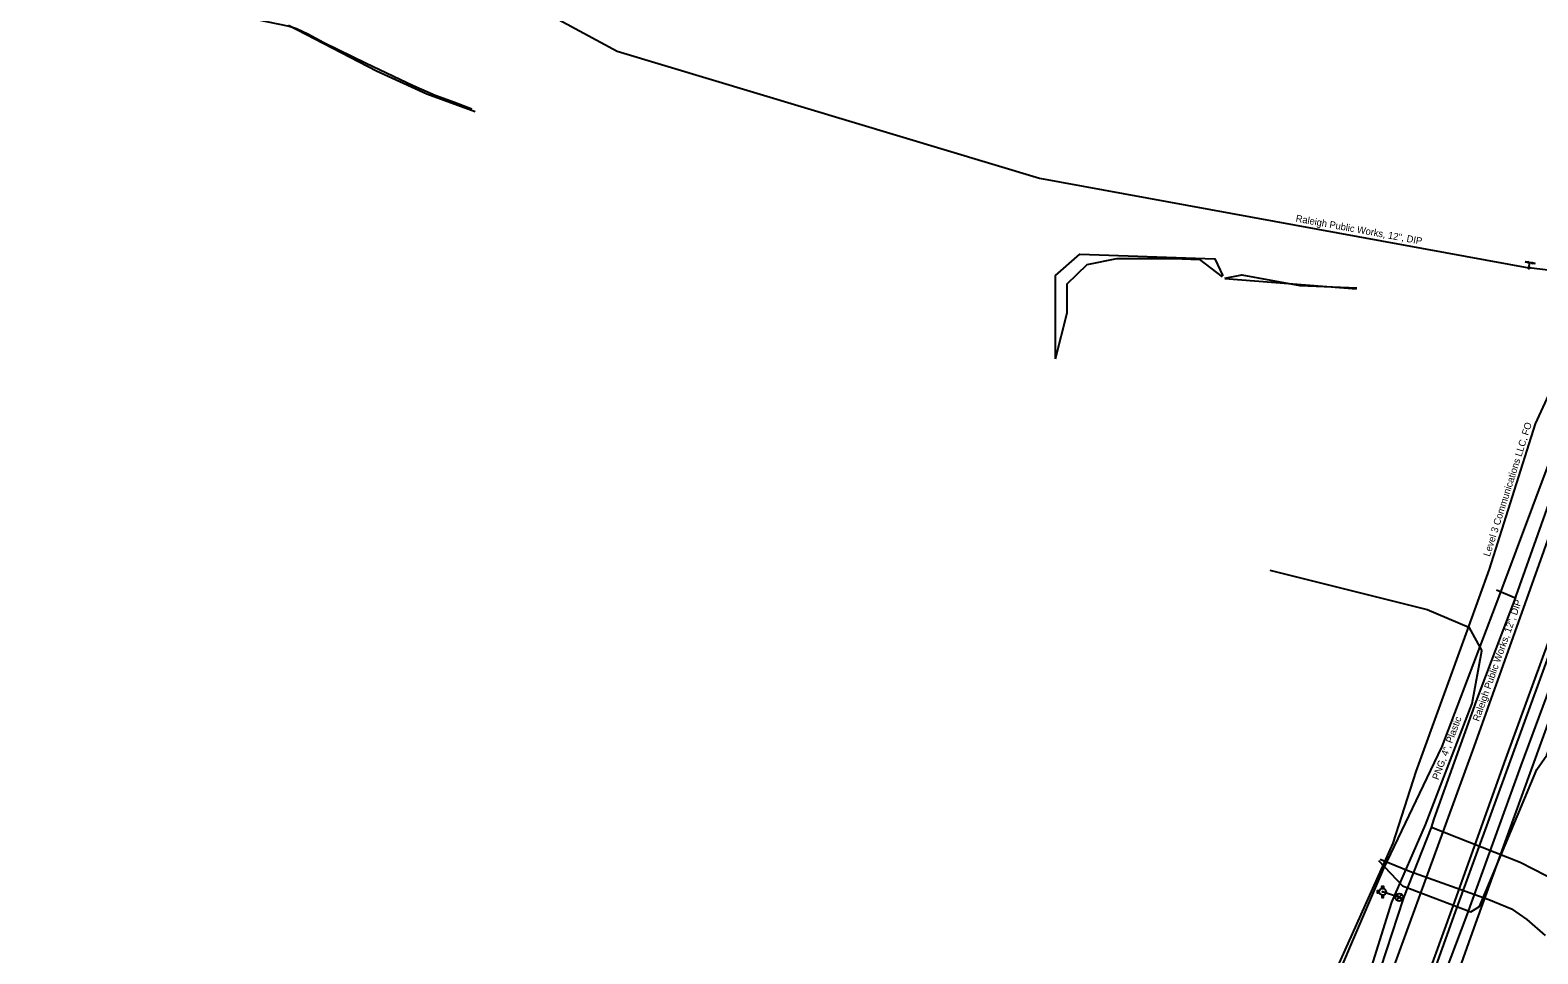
# Model space of a CAD drawing. Extents: x 2070721 to 2083340, y 729290 to 737883.
# Drawn here: x 2080348 to 2081213, y 733305 to 733835 of the extents above; entities that cross this region are included whole.
import ezdxf

# ---------------------------------------------------------------- set-up
doc = ezdxf.new("R2010")
doc.units = 0
for name, color, linetype in [('Exist Utilities Gas UG Line SUE LOS B', 7, 'Continuous'), ('Exist Utilities Gas UG Line SUE LOS B Text', 7, 'Continuous'), ('Exist Utilities Power UG Cable SUE LOS B', 7, 'Continuous'), ('Exist Utilities Telephone UG Cable SUE LOS C', 7, 'Continuous'), ('Exist Utilities Telephone UG FO SUE LOS B', 7, 'Continuous'), ('Exist Utilities Telephone UG FO SUE LOS B Text', 7, 'Continuous'), ('Exist Utilities TV UG Cable SUE LOS B', 7, 'Continuous'), ('Exist Utilities TV UG Cable SUE LOS C', 7, 'Continuous'), ('Exist Utilities TV UG FO Cable SUE LOS B', 7, 'Continuous'), ('Exist Utilities Water Change of Service SUE CELL', 7, 'Continuous'), ('Exist Utilities Water Fire Hydrant CELL', 7, 'Continuous'), ('Exist Utilities Water UG Line SUE LOS B', 7, 'Continuous'), ('Exist Utilities Water UG Line SUE LOS B Text', 7, 'Continuous'), ('Exist Utilities Water UG Line SUE LOS C', 7, 'Continuous'), ('Exist Utilities Water UG Line SUE LOS C Text', 7, 'Continuous'), ('Exist Utilities Water Valve CELL', 7, 'Continuous')]:
    doc.layers.add(name, color=color, linetype=linetype)

msp = doc.modelspace()

# ---------------------------------------------------------------- linework, layer by layer
at = {"layer": 'Exist Utilities Gas UG Line SUE LOS B'}
for points in [[(2081157.6, 733423.49), (2081157.75, 733423.93), (2081190.43, 733509.93), (2081219.7, 733588.19), (2081252.91, 733674.58), (2081286.02, 733770.88), (2081302.57, 733820.59), (2081312.47, 733846.89)], [(2080924.17, 732884.04), (2080930.33, 732882.17), (2080949.02, 732923.62), (2080986.84, 733002.49), (2081018.88, 733098.52), (2081046.79, 733177.28), (2081082.41, 733256.43), (2081124.09, 733353.56), (2081157.6, 733423.49)]]:
    msp.add_lwpolyline(points, dxfattribs=at)
at = {"layer": 'Exist Utilities Power UG Cable SUE LOS B'}
msp.add_line((2081108.69, 733686.24), (2081033.23, 733692.12), dxfattribs=at)
for points in [[(2081033.19, 733692.45), (2081042.88, 733694.33), (2081076.25, 733688.25), (2081108.94, 733687)], [(2081122.35, 733359.34), (2081139.09, 733352.49), (2081184.49, 733336.32), (2081197.51, 733330.86), (2081206.4, 733324.71), (2081216.97, 733315.56)]]:
    msp.add_lwpolyline(points, dxfattribs=at)
at = {"layer": 'Exist Utilities Telephone UG Cable SUE LOS C'}
for points in [[(2080953.21, 732796.69), (2081054.09, 733077.62), (2081111.09, 733245.57), (2081176.08, 733423.78), (2081231.97, 733580.28), (2081320.16, 733847.08), (2081418.84, 734093.09), (2081467.34, 734224.03), (2081494.06, 734287.2), (2081526.74, 734352.01), (2081556, 734404.62), (2081808.13, 734757.73), (2081845.73, 734804.26), (2081874.67, 734821.58), (2081898.66, 734810.94), (2081917.15, 734795.51)], [(2080936, 733646.3), (2080936, 733671.46), (2080936, 733693.97), (2080950.03, 733706.27), (2081027.4, 733703.51), (2081032.1, 733693.76)], [(2080936, 733646.3), (2080942.8, 733672.51), (2080942.8, 733689.3), (2080954.18, 733700.25), (2080971.23, 733703.78), (2081003.67, 733703.78), (2081018.65, 733703.13), (2081031.75, 733693.2)], [(2080971.45, 732791.05), (2081028.93, 732955.93), (2081037.58, 732965.12), (2081059.34, 733032.5), (2081099.5, 733145.5), (2081127.24, 733222.27), (2081165.53, 733329.08), (2081197.08, 733415.76), (2081225.51, 733493.81), (2081252.34, 733568.18), (2081252.65, 733568.73)], [(2080977.85, 732787.5), (2081009.55, 732879.6), (2081045.87, 732978.13), (2081063.56, 733030.35), (2081103.18, 733143.81), (2081131.57, 733220.23), (2081172.06, 733327.38), (2081203.1, 733413.05), (2081232.13, 733491.49), (2081257.07, 733565.11), (2081257.51, 733566.68)], [(2080980.31, 732787.04), (2081017.13, 732880.26), (2081044.65, 732962.53), (2081058.02, 732999.54), (2081069.26, 733036.84), (2081073.31, 733048.09), (2081079.75, 733057.99), (2081085.51, 733069.49), (2081110.84, 733140.06), (2081139.9, 733217.95), (2081177.19, 733322.59), (2081208.97, 733410.75), (2081237.5, 733489.4), (2081264.77, 733561.01)], [(2081059.04, 733525.1), (2081149.16, 733502.55), (2081173.19, 733492.4), (2081180.53, 733478.86)], [(2080944.31, 732798.44), (2080951.65, 732814.71), (2080971.81, 732874.01), (2081001.7, 732960.05), (2081020.52, 733019.4), (2081051.78, 733107.87), (2081085.75, 733202.6), (2081111.57, 733279.04), (2081128.94, 733334.77), (2081148.26, 733379.04), (2081175.1, 733448.52), (2081180.53, 733478.86)]]:
    msp.add_lwpolyline(points, dxfattribs=at)
at = {"layer": 'Exist Utilities Telephone UG FO SUE LOS B'}
for points in [[(2081060.57, 733214.24), (2081129.62, 733368.62), (2081142.99, 733409.6), (2081173.13, 733492.79), (2081185.02, 733525.68), (2081211.4, 733608.97), (2081237.57, 733665.91), (2081235.81, 733672.2)], [(2080974.54, 732788.58), (2081004.48, 732877.32), (2081038.77, 732975.1), (2081057.5, 733033.86), (2081097.09, 733146.25), (2081124.3, 733222.73), (2081163.35, 733330.31), (2081194.31, 733416.96), (2081222.79, 733494.92), (2081247.13, 733564.12), (2081248.81, 733567.64)]]:
    msp.add_lwpolyline(points, dxfattribs=at)
at = {"layer": 'Exist Utilities TV UG Cable SUE LOS B'}
msp.add_lwpolyline([(2081121.25, 733358.53), (2081135.11, 733344.16), (2081174.32, 733329.18), (2081179.16, 733332.24), (2081212.15, 733410.86), (2081217.78, 733418.98), (2081244.16, 733487.45), (2081271.85, 733556.1)], dxfattribs=at)
at = {"layer": 'Exist Utilities TV UG Cable SUE LOS C'}
msp.add_lwpolyline([(2080348.09, 733853.2), (2080390.88, 733858.86), (2080496.55, 733837.03), (2080500.76, 733835.64), (2080507.3, 733832.49), (2080516.48, 733827.67), (2080540.8, 733815.65), (2080567.67, 733802.85), (2080580.43, 733797.42), (2080591.34, 733793.44), (2080601.46, 733789.48)], dxfattribs=at)
at = {"layer": 'Exist Utilities TV UG FO Cable SUE LOS B'}
msp.add_lwpolyline([(2080496.25, 733837.52), (2080546.78, 733811.26), (2080575.54, 733798.17), (2080603.32, 733787.99)], dxfattribs=at)
at = {"layer": 'Exist Utilities Water Change of Service SUE CELL'}
for p, q in [((2081211.24, 733700.84), (2081205.37, 733701.91)), ((2081207.6, 733698.37), (2081208.15, 733701.4)), ((2081207.6, 733698.37), (2081207.6, 733698.37)), ((2081208.15, 733701.4), (2081211.24, 733700.84))]:
    msp.add_line(p, q, dxfattribs=at)
for points in [[(2081205.37, 733701.91), (2081207.37, 733701.9), (2081206.9, 733701.63), (2081207.22, 733701.26)], [(2081211.24, 733700.84), (2081209.24, 733700.86), (2081209.71, 733701.12), (2081209.39, 733701.49)]]:
    msp.add_lwpolyline(points, close=True, dxfattribs=at)
msp.add_circle((2081207.6, 733698.37), 0.517, dxfattribs=at)
at = {"layer": 'Exist Utilities Water Fire Hydrant CELL'}
msp.add_line((2081123.71, 733340.65), (2081123.71, 733340.65), dxfattribs=at)
for points in [[(2081121.8, 733341.17), (2081120.51, 733341.17), (2081120.51, 733340.14), (2081121.8, 733340.14)], [(2081123.2, 733342.57), (2081123.2, 733343.85), (2081124.22, 733343.85), (2081124.22, 733342.54)], [(2081123.2, 733338.74), (2081123.2, 733337.45), (2081124.22, 733337.45), (2081124.22, 733338.77)]]:
    msp.add_lwpolyline(points, dxfattribs=at)
for radius in [1.98, 0.243]:
    msp.add_circle((2081123.71, 733340.65), radius, dxfattribs=at)
at = {"layer": 'Exist Utilities Water UG Line SUE LOS B'}
msp.add_line((2081202.55, 733357.67), (2081234.51, 733341.1), dxfattribs=at)
for points in [[(2081265.37, 733690.97), (2081260.45, 733691.91), (2081207.6, 733698.37)], [(2081199.8, 733508.96), (2081200.26, 733510.4), (2081231.43, 733598.04), (2081246.63, 733639.55)], [(2081199.8, 733508.96), (2081199.23, 733509.2), (2081188.89, 733513.59)], [(2081151.65, 733377.59), (2081153.29, 733382.5), (2081177.58, 733450.17), (2081188.69, 733479.97), (2081199.8, 733508.96)], [(2081135.71, 733336.57), (2081136.04, 733337.71), (2081151.65, 733377.59)], [(2081151.69, 733377.7), (2081151.69, 733377.7), (2081202.55, 733357.67)], [(2081135.71, 733336.57), (2081133.78, 733337.11), (2081133.21, 733337.3), (2081123.72, 733340.66)], [(2080968.02, 732853.09), (2080971.09, 732863.55), (2080973.36, 732870.49), (2081004.03, 732959.14), (2081024.87, 733018.36), (2081055.27, 733107.45), (2081086.77, 733195.01), (2081116.19, 733277.07), (2081135.71, 733336.57)]]:
    msp.add_lwpolyline(points, dxfattribs=at)
at = {"layer": 'Exist Utilities Water UG Line SUE LOS C'}
msp.add_lwpolyline([(2080419.93, 733967.18), (2080512.22, 733915.86), (2080684.81, 733822.52), (2080926.94, 733749.77), (2081207.6, 733698.37)], dxfattribs=at)
at = {"layer": 'Exist Utilities Water Valve CELL'}
msp.add_lwpolyline([(2081134.76, 733339.06), (2081131.61, 733335.91), (2081133.18, 733337.48), (2081134.76, 733335.91), (2081131.61, 733339.06)], dxfattribs=at)
msp.add_circle((2081133.18, 733337.48), 2.23, dxfattribs=at)

# ---------------------------------------------------------------- texts
at = {"layer": 'Exist Utilities Gas UG Line SUE LOS B Text'}
msp.add_text('PNG, 4", Plastic', height=4, rotation=69.49347, dxfattribs=at).set_placement((2081155.66, 733404.49))
at = {"layer": 'Exist Utilities Telephone UG FO SUE LOS B Text'}
msp.add_text('Level 3 Communications LLC, FO', height=4, rotation=72.41985, dxfattribs=at).set_placement((2081185.1, 733532.57))
at = {"layer": 'Exist Utilities Water UG Line SUE LOS B Text'}
msp.add_text('Raleigh Public Works, 12", DIP', height=4, rotation=70.41855, dxfattribs=at).set_placement((2081178.91, 733438.03))
at = {"layer": 'Exist Utilities Water UG Line SUE LOS C Text'}
msp.add_text('Raleigh Public Works, 12", DIP', height=4, rotation=349.62108, dxfattribs=at).set_placement((2081073.6, 733724.94))

doc.saveas('drawing.dxf')
